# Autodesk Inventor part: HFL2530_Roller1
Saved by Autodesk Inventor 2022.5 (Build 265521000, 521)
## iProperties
Created: 2024-12
Part Number: HFL2530_Roller1
Material: Generic
Document SubType Name: Modeling
Designer: AdminForWorker
Density: 1 g/cm^3
Appearance: Default
Title: HFL2530_Roller1
Author: AdminForWorker
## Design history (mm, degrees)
feature "Body1"
body "Solid1"
